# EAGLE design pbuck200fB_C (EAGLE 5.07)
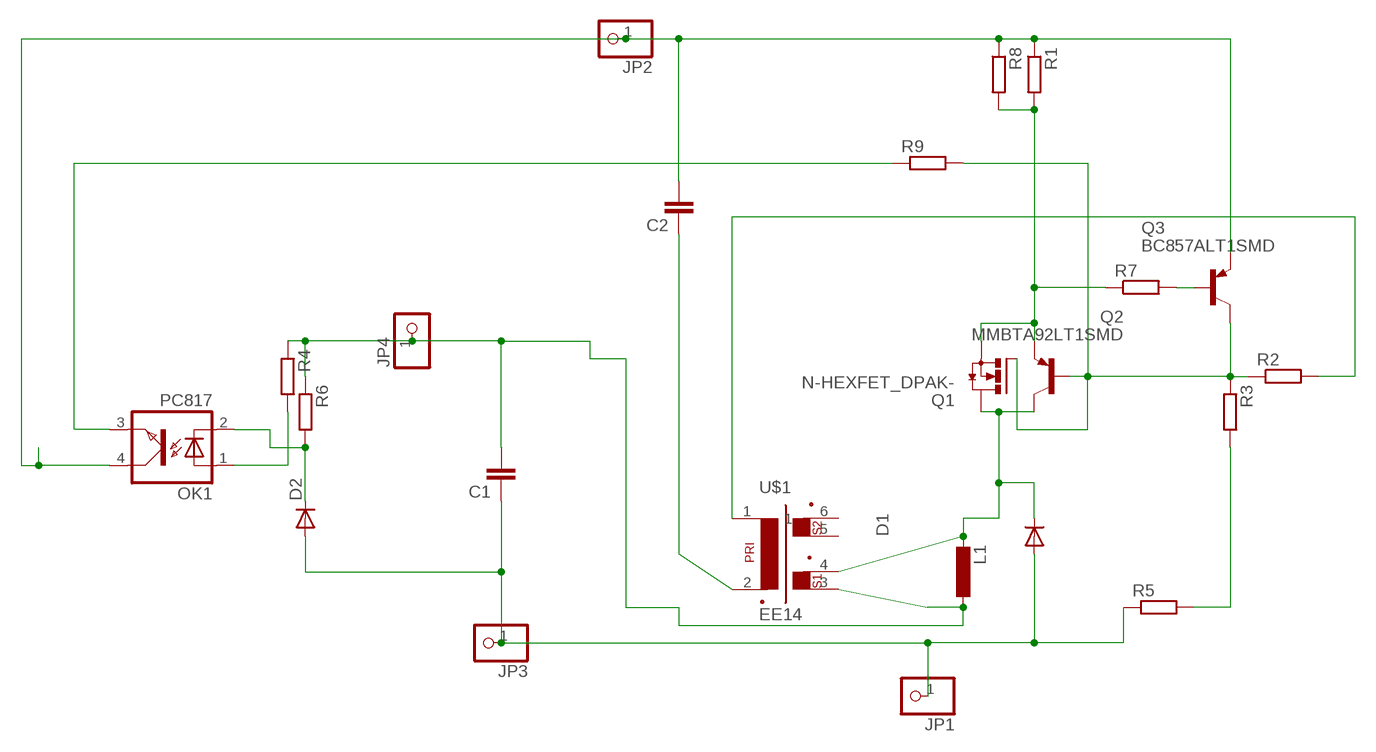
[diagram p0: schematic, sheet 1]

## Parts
C1  C-EU025-025X050  [C025-025X050]
C2  C-EUC0805  [C0805]
D1  DIODE-SMC  [SMC]
D2  DIODE-MINIMELF  [MINIMELF]
JP1  PINHD-1X11MM6  [1X1MM8]
JP2  PINHD-1X11MM6  [1X1MM8]
JP3  PINHD-1X11MM6  [1X1MM8]
JP4  PINHD-1X11MM6  [1X1MM8]
L1  L-EU0204/5  [0204/5]
OK1  PC817  [DIL04]
Q1  N-HEXFET_DPAK-  [TO252]
Q2  MMBTA92LT1SMD  [SOT23-BEC]
Q3  BC857ALT1SMD  [SOT23-BEC]
R1  R-EU_R1206  [R1206]
R2  R-EU_R0805  [R0805]
R3  R-EU_R1206  [R1206]
R4  R-EU_R0805  [R0805]
R5  R-EU_R1206  [R1206]
R6  R-EU_R0805  [R0805]
R7  R-EU_R1206  [R1206]
R8  R-EU_R1206  [R1206]
R9  R-EU_R0805  [R0805]
U$1  EE14  [EE14]

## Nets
-: C1.1 D1.A D2.A JP1.1 JP3.1 R5.1
B1C2: OK1.3(EMIT) R9.1
C1: D1.C L1.2 Q1.3(D) Q2.C U$1.4
EB: Q1.2(S) Q2.E R1.2 R7.1 R8.2
N$1: R3.2 R5.2
N$2: Q1.1(G) Q2.B Q3.C R2.1 R3.1 R9.2
N$3: Q3.B R7.2
N$4: R2.2 U$1.1
N$6: C2.1 U$1.2
N$7: D2.C OK1.2(C) R6.2
N$8: OK1.1(A) R4.2
OUT+: C1.2 JP4.1 L1.1 R4.1 R6.1 U$1.3
VPLUS: C2.2 JP2.1 OK1.4(COL) Q3.E R1.1 R8.1
Unconnected: U$1.5 U$1.6

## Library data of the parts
C1 C2 = rcl:C-EU: CAPACITOR, European symbol
D1 D2 = diode:DIODE-: DIODE
JP1-JP4 = pinhead:PINHD-1X1: PIN HEADER
L1 = rcl:L-EU: INDUCTOR, European symbol
OK1 = optocoupler:PC817: SHARP OPTO COUPLER
Q1 = transistor-power:N-HEXFET_?-*: HEXFET® Power MOSFET
Q2 = transistor-pnp:MMBTA92*: PNP Transistror
Q3 = transistor-pnp:BC857*: PNP Transistror
R1-R9 = rcl:R-EU_: RESISTOR, European symbol
U$1 = trafo:EE14

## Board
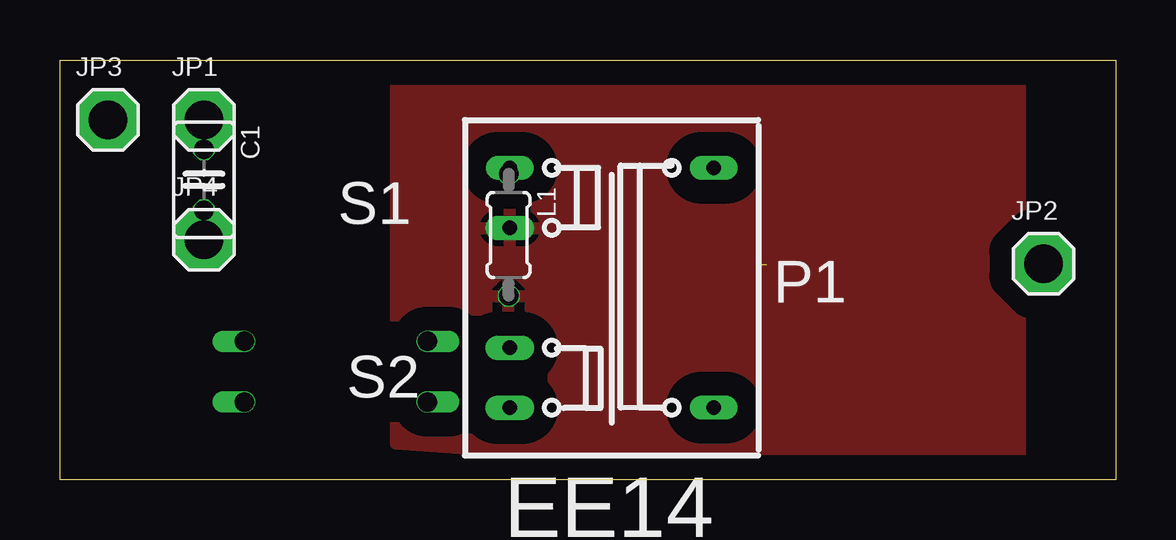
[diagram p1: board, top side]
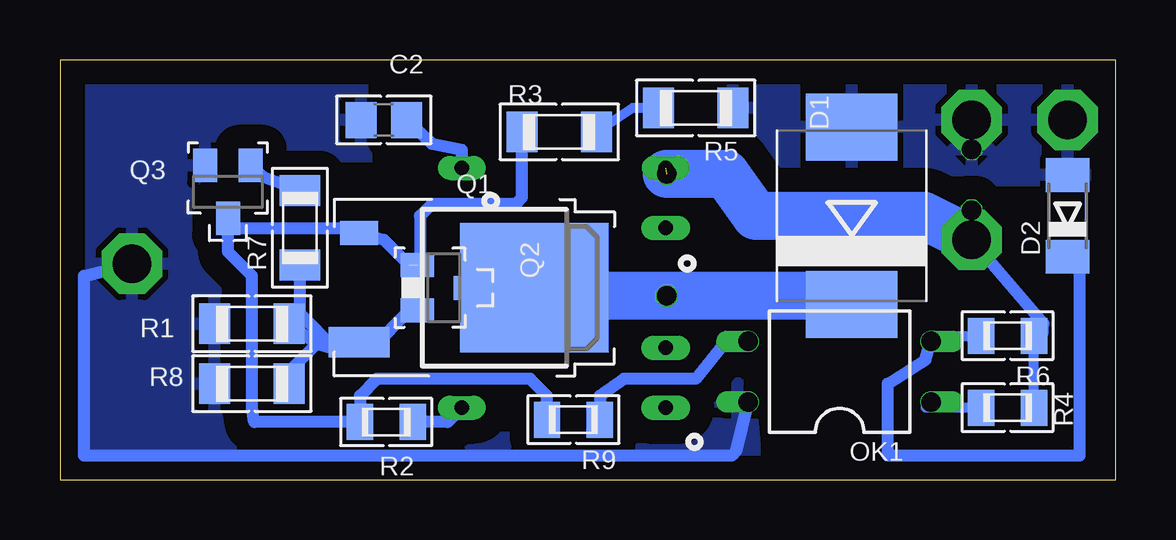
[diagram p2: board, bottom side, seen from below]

Size 44 x 17.5 mm. Coordinates in mm from the lower left corner, seen from the top.
Outline: 0,17.5 44,17.5 44,0 0,0 0,17.5
Copper layers (1*16): Top 0.035mm / dielectric 1.5mm / Bottom 0.035mm
Design rules "default": minimum track width 10mil, minimum drill 20mil, track to track 8mil, track to pad 8mil, pad to pad 8mil, via to via 8mil, smd to smd 8mil, copper to edge 40mil, drill to drill 8mil, minimum pad ring 1mil, minimum via ring 8mil, stop-mask expansion 4mil, vias tented up to drill 0mil, thermal gap 10mil

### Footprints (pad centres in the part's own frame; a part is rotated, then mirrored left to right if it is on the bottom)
C025-025X050 = drill 0.813 octagon: 1 -1.27,0; 2 1.27,0
C0805 = smd 1.3 x 1.5: 1 -0.95,0; 2 0.95,0
SMC = smd 2.8 x 3.8: A 3.7,0; C -3.7,0
MINIMELF = smd 1.4 x 1.8: A 1.7,0; C -1.7,0
1X1MM8 = drill 1.6 pad 2.54 octagon: 1 0,0
0204/5 = drill 0.813 octagon: 1 -2.54,0; 2 2.54,0
DIL04 = drill 0.813 offset: 1 -1.27,-3.81; 2 1.27,-3.81; 3 1.27,3.81; 4 -1.27,3.81
TO252 = smd 1 x 1.6: 1 -2.28,-3.53 | smd 1.27 x 2.54: 2 2.28,-3.53 | smd 5.4 x 6.2: 3 0,3.77
SOT23-BEC = smd 1 x 1.4: B -0.95,-1.1; C 0,1.1; E 0.95,-1.1
R1206 = smd 1.3 x 1.7: 1 -1.55,0; 2 1.55,0
R0805 = smd 1.1 x 1.5: 1 -1.1,0; 2 1.1,0
EE14 = drill 0.6 pad 1 long: 1 4.25,-5; 2 4.25,5; 3 -4.25,5 | drill 0.6 pad 1.016 long: 4 -4.25,2.5; 5 -4.25,-2.5; 6 -4.25,-5

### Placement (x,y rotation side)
C1  6,12.5 270 top
C2  30.5,15 180 bottom
D1  11,11 90 bottom
D2  2,11 90 bottom
JP1  6,15 0 top
JP2  41,9 0 top
JP3  2,15 0 top
JP4  6,10 0 top
L1  18.7,10.2 270 top
OK1  11.5,4.5 90 bottom
Q1  28,8 270 bottom
Q2  28,8 270 bottom
Q3  37,12 180 bottom
R1  36,6.5 0 bottom
R2  30.4,2.4 0 bottom
R3  23.19,14.5 0 bottom
R4  4.5,3 180 bottom
R5  17.5,15.5 180 bottom
R6  4.5,6 180 bottom
R7  34,10.5 90 bottom
R8  36,4 0 bottom
R9  22.6,2.5 180 bottom
U$1  23,8 0 top

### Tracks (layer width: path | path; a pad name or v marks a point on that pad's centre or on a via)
-
  pour Bottom (isolate 1, rank 2): 1.5,16.5 16,16.5 16,13.5 15,12.5 1,12.5
B1C2
  Bottom 0.5: OK1.3 16.23,5.77 17.5,4.2 20.5,4.2 21.5,3.5 R9.1
C1
  Bottom 0.406: 24.14,7.66 Q1.3 25.49,7.87 26.65,7.75
  Bottom 0.5: L1.2 18.56,7.8 | D1.C 11.14,7.66 | Q2.C 25.62,8 25.49,7.87
  Bottom 2: 11.14,7.66 L1.2 24.14,7.66
  pour Top (isolate 1, rank 2): 14,16.5 40,16.5 40,1 21,1 14,1.5
EB
  Bottom 0.406: 31.5,5.4 30.74,5.4 30.67,5.47
  Bottom 0.5: 30.67,5.47 Q1.2 31.5,5.5 31,5.5 29.45,7.05 Q2.E | 31.5,5.4 32.5,5.43 | 32.5,5.43 33.3,5.67 | 33.3,5.67 R1.2 | R7.1 34,6.93 32.5,5.43 | R8.2 34.45,4.52 33.3,5.67
N$1
  Bottom 0.406: R5.2 20.13,15.5 R3.2
N$2  (1 unrouted)
  Bottom 0.5: R3.1 24.74,11.76 25,11.5 28.5,11.5 29,11 29,9.05 Q2.B | 29.45,8.95 30.5,10 32,10.5 | 32,10.5 Q1.1 | R9.2 23.7,3.5 24.4,4.2 30.8,4.2 31.5,3.5 R2.1 35.9,2.4 36,3 36,8.5 37,9.5 Q3.C 37.1,10.5 32,10.5
N$3
  Bottom 0.5: R7.2 35.5,12.6 Q3.B
N$4
  Bottom 0.5: R2.2 27.85,2.4 U$1.1
N$6
  Bottom 0.5: U$1.2 27.25,13.75 28.5,14 C2.1
N$7
  Bottom 0.406: R6.2 7.46,6 OK1.2
  Bottom 0.5: OK1.2 7.92,5 9.5,4 9.5,1 1.5,1 1.5,9 1.8,9.3 D2.C
N$8
  Bottom 0.406: R4.2 7.92,3 OK1.1
OUT+  (1 unrouted)
  Bottom 0.406: 3,6.5 3,6.1 R6.1 R4.1
  Bottom 0.5: C1.2 JP4.1 3,6.5
  Bottom 2: JP4.1 8,11 15,11 16.24,12.74 L1.1
VPLUS
  Bottom 0.5: JP2.1 43,8.5 43,1 16,1 15.81,1.19 OK1.4
  pour Bottom (isolate 1, rank 3): 31.5,17 43.5,17 44,1 15,1 15.5,6.5 36.5,6.5 36.5,12.5 36,13.5 31,13.5 31,16.5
